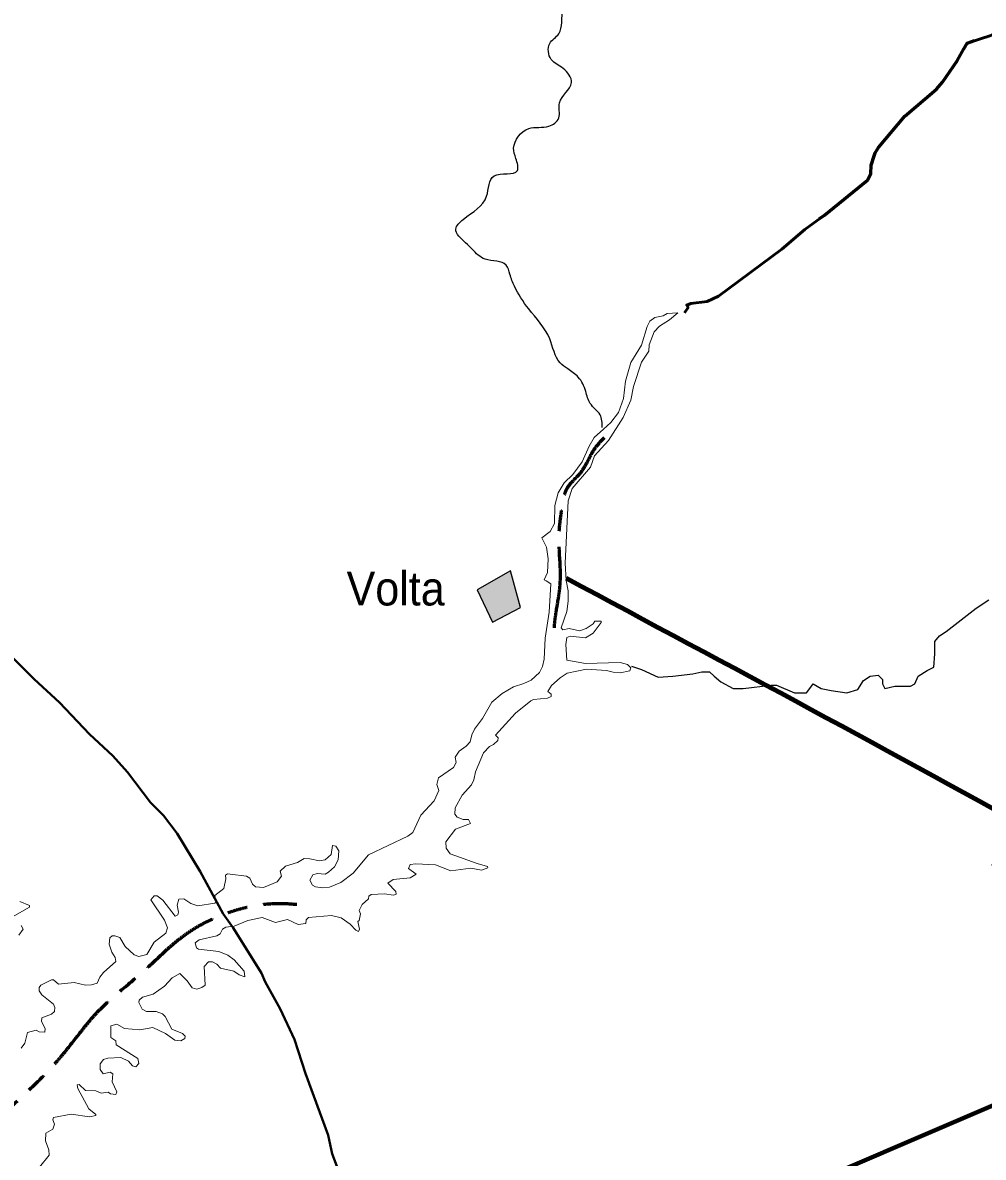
# Model space of a CAD drawing. Extents: x 553962 to 842807, y 8883888 to 9032388.
# Drawn here: x 584685 to 598851, y 8968659 to 8985392 of the extents above; entities that cross this region are included whole.
import ezdxf

# ---------------------------------------------------------------- set-up
doc = ezdxf.new("R2010")
doc.units = 0
doc.header["$LTSCALE"] = 200
doc.linetypes.add('LONG_DASH_SHORT_DASH', pattern=[9.9, 6, -1.2, 1.5, -1.2])
for name, color, linetype, lineweight in [('12', 7, 'Continuous', 25), ('21', 7, 'Continuous', 25), ('24', 7, 'Continuous', 25), ('25', 7, 'Continuous', 13), ('28', 7, 'Continuous', 40), ('41', 7, 'Continuous', 40), ('7', 7, 'LONG_DASH_SHORT_DASH', 60), ('9', 7, 'Continuous', 90)]:
    doc.layers.add(name, color=color, linetype=linetype, lineweight=lineweight)

msp = doc.modelspace()

# ---------------------------------------------------------------- hatches: boundary and pattern name
at = {"layer": '21'}
msp.add_hatch(color=256, dxfattribs=at).paths.add_polyline_path([(591387.2, 8977029.8), (591614.3, 8976550.1), (592028.7, 8976768.6), (591880.1, 8977309.9)])

# ---------------------------------------------------------------- linework, layer by layer
at = {"layer": '12', "lineweight": 40}
msp.add_lwpolyline([(584414.4, 8976152.1), (584852.4, 8975709.9), (585227.8, 8975368.9), (585671, 8974897.7), (586014.6, 8974582.2), (586230.8, 8974340.1), (586568.3, 8973894.4), (586761.1, 8973701.7), (586961.6, 8973436.3), (587301, 8972874.3), (587640.4, 8972251.7), (587788.5, 8972042.4), (588207.4, 8971376.7), (588263.1, 8971248.8), (588483.5, 8970850.8), (588695.4, 8970396.6), (588857.5, 8969895.4), (589190.3, 8968987.7), (589251, 8968710.7), (589674.6, 8967582.3)], dxfattribs=at)
at = {"layer": '21'}
msp.add_lwpolyline([(591387.2, 8977029.8), (591614.3, 8976550.1), (592028.7, 8976768.6), (591880.1, 8977309.9)], close=True, dxfattribs=at)
at = {"layer": '24', "lineweight": 53}
for points in [[(598562.6, 8985004.4), (598611, 8985091.4), (598961, 8985203.4), (599114.5, 8985297), (599176.5, 8985365.4)], [(597241.4, 8983430.3), (597255.2, 8983474), (597303.8, 8983551.2), (597693.6, 8984012), (598158.8, 8984413.5), (598250.1, 8984513.3), (598466.9, 8984832.2), (598562.6, 8985004.4)], [(597144.4, 8983071.7), (597192.6, 8983165.7), (597196.6, 8983289.5), (597241.4, 8983430.3)], [(594445, 8981112.5), (594498.6, 8981193.2), (594478.9, 8981228.6), (594539.1, 8981252.5), (594781.2, 8981282.3), (594943.8, 8981357.5), (595881.6, 8982053.4), (596221.2, 8982344.2), (596509.3, 8982553.5), (597144.4, 8983071.7)]]:
    msp.add_lwpolyline(points, dxfattribs=at)
at = {"layer": '24'}
msp.add_lwpolyline([(593663, 8975903.4), (593811, 8975854), (594057.8, 8975738.8), (594271.7, 8975755.3), (594567.8, 8975788.2), (594699.4, 8975821.1), (594814.5, 8975821.1), (594880.3, 8975755.3), (594979, 8975673), (595160, 8975574.2), (595308.1, 8975574.2), (595719.3, 8975623.6), (595801.6, 8975623.6), (596064.8, 8975508.3), (596163.5, 8975508.3), (596245.7, 8975508.3), (596295.1, 8975574.2), (596344.4, 8975640), (596459.6, 8975574.2), (596607.7, 8975541.3), (596838, 8975508.3), (597002.5, 8975557.7), (597084.7, 8975689.4), (597183.4, 8975755.3), (597298.6, 8975771.7), (597364.4, 8975705.9), (597364.4, 8975640), (597397.3, 8975574.2), (597545.3, 8975607.1), (597627.6, 8975607.1), (597775.7, 8975607.1), (597841.5, 8975640), (597890.8, 8975755.3), (598022.4, 8975837.6), (598121.1, 8975887), (598137.6, 8976084.5), (598137.6, 8976265.6), (598203.4, 8976347.9), (598302.1, 8976413.7), (598746.2, 8976759.4), (598932.5, 8976878.8)], dxfattribs=at)
msp.add_spline([(593232.1, 8979422.6), (593198.8, 8979610.9), (593054.8, 8979777.1), (592988.4, 8979954.4), (592877.6, 8980164.9), (592722.6, 8980286.8), (592611.8, 8980375.4), (592456.8, 8980729.9), (592146.7, 8981173.1), (591936.2, 8981505.4), (591869.8, 8981682.7), (591814.4, 8981815.7), (591504.3, 8981904.3), (591316, 8982048.3), (591216.4, 8982148), (591072.4, 8982347.5), (591183.1, 8982491.5), (591526.5, 8982834.9), (591637.2, 8983134.1), (591980.6, 8983211.6), (591958.4, 8983388.9), (591925.2, 8983544), (592146.7, 8983832), (592445.7, 8983865.3), (592589.7, 8983987.2), (592600.8, 8984208.7), (592778, 8984507.9), (592656.1, 8984718.4), (592478.9, 8984851.3), (592456.8, 8985084), (592589.7, 8985228), (592634, 8985394.2), (592645.1, 8985826.3), (592645.1, 8985970.3), (592467.9, 8986191.9), (592423.5, 8986763.6), (592224.2, 8987206.8), (592124.5, 8987461.6), (591847.6, 8987760.7), (591604, 8988037.7), (591482.1, 8988436.5), (591360.3, 8988702.4), (590950.5, 8989079.1), (590806.6, 8989256.4), (590518.6, 8989245.3), (590341.4, 8989422.6), (590031.3, 8989610.9), (589676.9, 8989721.7)], degree=3, dxfattribs=at)
at = {"layer": '25'}
for points in [[(594348, 8981113.9), (594348, 8981113.9), (594223.4, 8981008.9), (594075.8, 8980918.9), (593999.5, 8980834.1), (593923.2, 8980641.1), (593918.7, 8980549.5), (593810.5, 8980383.8), (593691.6, 8980027.2), (593653.2, 8979823), (593541.1, 8979568.9), (593541.1, 8979568.9), (593326.1, 8979230.3), (593118.1, 8979003.2), (593056.2, 8978837.1), (592788.7, 8978522.9), (592727, 8978339.3), (592684.6, 8977422.8), (592701.6, 8977167.9), (592731.3, 8977014.7), (592731.4, 8976862.7), (592710.1, 8976709.1), (592625.3, 8976466.7), (592653, 8976439.2), (592742.2, 8976458.1), (592894.9, 8976424.2), (592992.8, 8976460.4), (593098.8, 8976528.3), (593123.6, 8976567.4), (593214.3, 8976567.6), (593214.6, 8976559.7)], [(594348, 8981113.9), (594348, 8981113.9), (594223.4, 8981008.9), (594075.8, 8980918.9), (593999.5, 8980834.1), (593923.2, 8980641.1), (593918.7, 8980549.5), (593810.5, 8980383.8), (593691.6, 8980027.2), (593653.2, 8979823), (593541.1, 8979568.9), (593541.1, 8979568.9), (593326.1, 8979230.3), (593118.1, 8979003.2), (593056.2, 8978837.1), (592788.7, 8978522.9), (592727, 8978339.3), (592684.6, 8977422.8), (592701.6, 8977167.9), (592731.3, 8977014.7), (592731.4, 8976862.7), (592710.1, 8976709.1), (592625.3, 8976466.7), (592653, 8976439.2), (592742.2, 8976458.1), (592894.9, 8976424.2), (592992.8, 8976460.4), (593098.8, 8976528.3), (593123.6, 8976567.4), (593214.3, 8976567.6), (593214.6, 8976559.7)], [(593249.5, 8979396.5), (593358, 8979493.7), (593470.6, 8979644.5), (593544.9, 8979848.5), (593574.7, 8980103.6), (593653.1, 8980383.1), (593812.7, 8980635), (593893.2, 8980910.4), (593931.4, 8980988.9), (594007.8, 8981044.3), (594131.2, 8981067.8), (594188.7, 8981102), (594348, 8981113.9)], [(593249.5, 8979396.5), (593358, 8979493.7), (593470.6, 8979644.5), (593544.9, 8979848.5), (593574.7, 8980103.6), (593653.1, 8980383.1), (593812.7, 8980635), (593893.2, 8980910.4), (593931.4, 8980988.9), (594007.8, 8981044.3), (594131.2, 8981067.8), (594188.7, 8981102), (594348, 8981113.9)], [(592340.2, 8977796.1), (592463.6, 8977889.9), (592529.4, 8978006.6), (592531.7, 8978272), (592582.8, 8978459.4), (592672, 8978608.1), (592799.5, 8978729.2), (592937.2, 8978913.6), (593037.2, 8979147.4), (593113.6, 8979274.7), (593249.5, 8979396.5)], [(592340.2, 8977796.1), (592463.6, 8977889.9), (592529.4, 8978006.6), (592531.7, 8978272), (592582.8, 8978459.4), (592672, 8978608.1), (592799.5, 8978729.2), (592937.2, 8978913.6), (593037.2, 8979147.4), (593113.6, 8979274.7), (593249.5, 8979396.5)], [(592403.5, 8977160.8), (592376.8, 8977178.1), (592423.3, 8977282.6), (592436.1, 8977486), (592410.8, 8977655.4), (592340.2, 8977796.1)], [(592403.5, 8977160.8), (592376.8, 8977178.1), (592423.3, 8977282.6), (592436.1, 8977486), (592410.8, 8977655.4), (592340.2, 8977796.1)], [(589256.8, 8973257.4), (589304.8, 8973250.5), (589349.5, 8973181.3), (589336.7, 8973046.6), (589282, 8972943.2), (589197.1, 8972864.3), (589143.7, 8972836.4), (589028.8, 8972846.9), (588963.2, 8972823.6), (588920.5, 8972745), (588956.7, 8972674.9), (589003.3, 8972647.2), (589105, 8972632.4), (589208.9, 8972641.3), (589377.1, 8972711), (589557.5, 8972848.9), (589783.1, 8973121.1), (590364.9, 8973397.1), (590439.2, 8973448.1), (590558.2, 8973707.2), (590751.6, 8973917.8), (590821.5, 8974070.5), (590792, 8974157.8), (590815.2, 8974257.2), (591040.4, 8974410.4), (591076.5, 8974482.4), (591063.8, 8974558.8), (591121.2, 8974648.3), (591227.2, 8974720.4), (591282.6, 8974788.8), (591308.2, 8974890.7), (591350.1, 8974974.6), (591465.3, 8975128.4), (591603.2, 8975370.3), (591756.1, 8975500), (591922, 8975597.8), (592075.7, 8975644.8), (592185.6, 8975697.8), (592308.6, 8975810.4), (592349.1, 8975899.9), (592374.4, 8976007.6), (592391.5, 8976313.7), (592449, 8976697.9), (592471.9, 8977116.8), (592403.5, 8977160.8)], [(589256.8, 8973257.4), (589304.8, 8973250.5), (589349.5, 8973181.3), (589336.7, 8973046.6), (589282, 8972943.2), (589197.1, 8972864.3), (589143.7, 8972836.4), (589028.8, 8972846.9), (588963.2, 8972823.6), (588920.5, 8972745), (588956.7, 8972674.9), (589003.3, 8972647.2), (589105, 8972632.4), (589208.9, 8972641.3), (589377.1, 8972711), (589557.5, 8972848.9), (589783.1, 8973121.1), (590364.9, 8973397.1), (590439.2, 8973448.1), (590558.2, 8973707.2), (590751.6, 8973917.8), (590821.5, 8974070.5), (590792, 8974157.8), (590815.2, 8974257.2), (591040.4, 8974410.4), (591076.5, 8974482.4), (591063.8, 8974558.8), (591121.2, 8974648.3), (591227.2, 8974720.4), (591282.6, 8974788.8), (591308.2, 8974890.7), (591350.1, 8974974.6), (591465.3, 8975128.4), (591603.2, 8975370.3), (591756.1, 8975500), (591922, 8975597.8), (592075.7, 8975644.8), (592185.6, 8975697.8), (592308.6, 8975810.4), (592349.1, 8975899.9), (592374.4, 8976007.6), (592391.5, 8976313.7), (592449, 8976697.9), (592471.9, 8977116.8), (592403.5, 8977160.8)], [(593214.6, 8976559.7), (593215.2, 8976544.7), (593099, 8976390.4), (592986.9, 8976322.5), (592758.7, 8976343.4), (592708.2, 8976324.4), (592695.2, 8976224.5), (592709.9, 8975991.5), (592983.9, 8975944.1), (593493.9, 8975956.8), (593602.1, 8975927.4), (593649.1, 8975881.7)], [(593214.6, 8976559.7), (593215.2, 8976544.7), (593099, 8976390.4), (592986.9, 8976322.5), (592758.7, 8976343.4), (592708.2, 8976324.4), (592695.2, 8976224.5), (592709.9, 8975991.5), (592983.9, 8975944.1), (593493.9, 8975956.8), (593602.1, 8975927.4), (593649.1, 8975881.7)], [(593649.1, 8975881.7), (593655, 8975876), (593638.1, 8975835.7), (593493.9, 8975806), (593392, 8975812.4), (593294, 8975840), (593001.4, 8975857), (592713.8, 8975797.2), (592610.3, 8975731.6), (592482.8, 8975616.5), (592429.9, 8975529.9), (592480.5, 8975487.5), (592478.3, 8975455.5), (592423.1, 8975432.1), (592219.4, 8975410.8), (592178.8, 8975393.7), (591951.5, 8975211), (591658.9, 8974884.4), (591696.9, 8974843.5), (591690.4, 8974805.5), (591629, 8974746.2), (591569.4, 8974716.2), (591482.2, 8974622.5), (591361.3, 8974342.6), (591339.9, 8974225.6), (591302.4, 8974150.2), (591167.7, 8974002.3), (591061.7, 8973815.6), (591059.6, 8973722.4), (591091.3, 8973677.8), (591182.8, 8973643.6), (591261.3, 8973639.2), (591286.8, 8973584.3), (591065.8, 8973500.9), (590925.8, 8973310), (590930.2, 8973216.3), (590989.7, 8973133.6), (591386.4, 8972993.6), (591539.1, 8972948.4), (591544.1, 8972929.1)], [(593649.1, 8975881.7), (593655, 8975876), (593638.1, 8975835.7), (593493.9, 8975806), (593392, 8975812.4), (593294, 8975840), (593001.4, 8975857), (592713.8, 8975797.2), (592610.3, 8975731.6), (592482.8, 8975616.5), (592429.9, 8975529.9), (592480.5, 8975487.5), (592478.3, 8975455.5), (592423.1, 8975432.1), (592219.4, 8975410.8), (592178.8, 8975393.7), (591951.5, 8975211), (591658.9, 8974884.4), (591696.9, 8974843.5), (591690.4, 8974805.5), (591629, 8974746.2), (591569.4, 8974716.2), (591482.2, 8974622.5), (591361.3, 8974342.6), (591339.9, 8974225.6), (591302.4, 8974150.2), (591167.7, 8974002.3), (591061.7, 8973815.6), (591059.6, 8973722.4), (591091.3, 8973677.8), (591182.8, 8973643.6), (591261.3, 8973639.2), (591286.8, 8973584.3), (591065.8, 8973500.9), (590925.8, 8973310), (590930.2, 8973216.3), (590989.7, 8973133.6), (591386.4, 8972993.6), (591539.1, 8972948.4), (591544.1, 8972929.1)], [(587744.4, 8972835.9), (587983.9, 8972804.3), (588036.8, 8972776.6), (588075, 8972687.6), (588119.6, 8972647.3), (588237.5, 8972640.8), (588435.9, 8972723.7), (588499.7, 8972804.5), (588483.1, 8972879), (588561.7, 8972951.1), (588739.8, 8973006.3), (588835.7, 8973065.7), (588918.6, 8973063.5), (589063, 8973031.8), (589147.9, 8973046.8), (589234.5, 8973124.8), (589252.7, 8973258), (589256.8, 8973257.4)], [(587744.4, 8972835.9), (587983.9, 8972804.3), (588036.8, 8972776.6), (588075, 8972687.6), (588119.6, 8972647.3), (588237.5, 8972640.8), (588435.9, 8972723.7), (588499.7, 8972804.5), (588483.1, 8972879), (588561.7, 8972951.1), (588739.8, 8973006.3), (588835.7, 8973065.7), (588918.6, 8973063.5), (589063, 8973031.8), (589147.9, 8973046.8), (589234.5, 8973124.8), (589252.7, 8973258), (589256.8, 8973257.4)], [(591544.1, 8972929.1), (591451.2, 8972895.9), (591293, 8972921.2), (591000.3, 8972885.2), (590771.4, 8972974.2), (590482, 8972987.1), (590400.9, 8972976.4), (590375.5, 8972917.5), (590487.9, 8972834.1), (590400.8, 8972781.1), (590146.4, 8972755.6), (590069.9, 8972700.4), (590188.4, 8972581.5), (590190.6, 8972539), (590153.7, 8972526.2), (590022.9, 8972543.1), (589823.3, 8972534.6), (589789.5, 8972511.4), (589784.9, 8972471), (589689.6, 8972386.1), (589647, 8972301.2), (589666, 8972251.4), (589644.9, 8972152.7), (589627.8, 8972139.3), (589651.2, 8972025), (589636.7, 8971991.2), (589636.7, 8971991.2)], [(591544.1, 8972929.1), (591451.2, 8972895.9), (591293, 8972921.2), (591000.3, 8972885.2), (590771.4, 8972974.2), (590482, 8972987.1), (590400.9, 8972976.4), (590375.5, 8972917.5), (590487.9, 8972834.1), (590400.8, 8972781.1), (590146.4, 8972755.6), (590069.9, 8972700.4), (590188.4, 8972581.5), (590190.6, 8972539), (590153.7, 8972526.2), (590022.9, 8972543.1), (589823.3, 8972534.6), (589789.5, 8972511.4), (589784.9, 8972471), (589689.6, 8972386.1), (589647, 8972301.2), (589666, 8972251.4), (589644.9, 8972152.7), (589627.8, 8972139.3), (589651.2, 8972025), (589636.7, 8971991.2), (589636.7, 8971991.2)], [(585111.6, 8971279.2), (585141.3, 8971274.9), (585213.8, 8971211.3), (585443, 8971236.7), (585613.2, 8971196.4), (585698.2, 8971200.7), (585782.6, 8971228.1), (585821.2, 8971315.3), (585878.5, 8971385.4), (586058.9, 8971546.7), (586050.5, 8971606.3), (585999.6, 8971687.1), (585961.4, 8971801.8), (585969.8, 8971897.1), (586004, 8971925.1), (586046.1, 8971927.1), (586118.5, 8971901.5), (586197.3, 8971767.6), (586326.8, 8971644.7), (586399.8, 8971621.3), (586515.7, 8971651), (586626.4, 8971831.7), (586793.9, 8971963.1), (586819.5, 8972043.7), (586777.5, 8972158), (586575.5, 8972456.3), (586626.1, 8972513.3), (586666.5, 8972513.3), (586751.7, 8972453.7), (586934.4, 8972216.2), (586974.5, 8972237.3), (586982.9, 8972274.7), (586964.1, 8972379.9), (586989.7, 8972468.8), (587061.7, 8972470.9), (587164.3, 8972404.8), (587265.6, 8972369), (587521, 8972409.7), (587521, 8972409.7), (587537.4, 8972424.4), (587520.6, 8972519.8), (587652.2, 8972626), (587681.8, 8972766), (587674.8, 8972821.7), (587705.8, 8972841), (587744.4, 8972835.9)], [(585111.6, 8971279.2), (585141.3, 8971274.9), (585213.8, 8971211.3), (585443, 8971236.7), (585613.2, 8971196.4), (585698.2, 8971200.7), (585782.6, 8971228.1), (585821.2, 8971315.3), (585878.5, 8971385.4), (586058.9, 8971546.7), (586050.5, 8971606.3), (585999.6, 8971687.1), (585961.4, 8971801.8), (585969.8, 8971897.1), (586004, 8971925.1), (586046.1, 8971927.1), (586118.5, 8971901.5), (586197.3, 8971767.6), (586326.8, 8971644.7), (586399.8, 8971621.3), (586515.7, 8971651), (586626.4, 8971831.7), (586793.9, 8971963.1), (586819.5, 8972043.7), (586777.5, 8972158), (586575.5, 8972456.3), (586626.1, 8972513.3), (586666.5, 8972513.3), (586751.7, 8972453.7), (586934.4, 8972216.2), (586974.5, 8972237.3), (586982.9, 8972274.7), (586964.1, 8972379.9), (586989.7, 8972468.8), (587061.7, 8972470.9), (587164.3, 8972404.8), (587265.6, 8972369), (587521, 8972409.7), (587521, 8972409.7), (587537.4, 8972424.4), (587520.6, 8972519.8), (587652.2, 8972626), (587681.8, 8972766), (587674.8, 8972821.7), (587705.8, 8972841), (587744.4, 8972835.9)], [(584644.6, 8972432.6), (584786.6, 8972370.8), (584785.8, 8972347.3), (584395, 8972126.3)], [(584644.6, 8972432.6), (584786.6, 8972370.8), (584785.8, 8972347.3), (584395, 8972126.3)], [(589636.7, 8971991.2), (589598.1, 8972007.9), (589513.3, 8972099), (589381.6, 8972192.5), (589241.4, 8972224.5), (588901.3, 8972196.8), (588865.3, 8972162.9), (588863, 8972107.8), (588748.1, 8972092.9), (588748.1, 8972092.9), (588590.9, 8972165), (588412.8, 8972122.6), (588217.3, 8972196.9), (588004.9, 8972152.3), (587806, 8972067.6), (587682, 8972052.4), (587633.2, 8972022.7), (587596.9, 8971954.8), (587546.7, 8971925.3), (587289, 8971866.3), (587229.6, 8971820.7), (587248.6, 8971751), (587275.8, 8971727.9), (587576, 8971693.4), (587711.7, 8971638.2), (587803.3, 8971572.2), (587950.9, 8971402.7), (587960.4, 8971321.1)], [(589636.7, 8971991.2), (589598.1, 8972007.9), (589513.3, 8972099), (589381.6, 8972192.5), (589241.4, 8972224.5), (588901.3, 8972196.8), (588865.3, 8972162.9), (588863, 8972107.8), (588748.1, 8972092.9), (588748.1, 8972092.9), (588590.9, 8972165), (588412.8, 8972122.6), (588217.3, 8972196.9), (588004.9, 8972152.3), (587806, 8972067.6), (587682, 8972052.4), (587633.2, 8972022.7), (587596.9, 8971954.8), (587546.7, 8971925.3), (587289, 8971866.3), (587229.6, 8971820.7), (587248.6, 8971751), (587275.8, 8971727.9), (587576, 8971693.4), (587711.7, 8971638.2), (587803.3, 8971572.2), (587950.9, 8971402.7), (587960.4, 8971321.1)], [(584661.4, 8972077.8), (584690.8, 8972022.3), (584629.4, 8971933.2)], [(584661.4, 8972077.8), (584690.8, 8972022.3), (584629.4, 8971933.2)], [(587960.4, 8971321.1), (587960.4, 8971321.1), (587878.2, 8971348.9), (587800.7, 8971404.6), (587601.6, 8971447), (587546.2, 8971506.3), (587484.6, 8971544.6), (587424.8, 8971542.6), (587359.2, 8971474.4), (587373.9, 8971198.8), (587329.3, 8971162.4), (587253.1, 8971141.2), (587184.9, 8971158.2), (587112.5, 8971262.4), (587002, 8971368.3), (586889.7, 8971306.8), (586777.2, 8971181.7), (586606.9, 8971064.6), (586453.7, 8971019.6), (586403.3, 8970977.5), (586399, 8970942.1), (586445.6, 8970844.1), (586509.4, 8970807.7), (586653.8, 8970811.9), (586747.1, 8970773.8), (586785.6, 8970735.2), (586885.5, 8970550.7), (587042.4, 8970487), (587082.7, 8970444.8), (587078.6, 8970412.6), (587019.2, 8970376.5), (586928.2, 8970384.9), (586793.3, 8970485.2), (586602.9, 8970571.8), (586411.7, 8970540), (586184.3, 8970557.1), (586072, 8970620.6), (585986.8, 8970597.1), (585985.1, 8970426.9), (586057, 8970376.2), (586064.4, 8970318.2), (586383.6, 8970117.6), (586398.9, 8970043.2), (586352.2, 8969994.2), (586303.6, 8970008.9), (586245.3, 8970079.5), (586131.1, 8970130), (585940.1, 8970123.6), (585874.5, 8970100.3), (585827.6, 8970038.4), (585830, 8969952.9), (585872.2, 8969890), (585973.9, 8969915.4), (586012.3, 8969889.7), (586006, 8969772.9), (586071.7, 8969626.7), (586056.7, 8969586.3), (585978.4, 8969594.8), (585945.9, 8969618), (585842.4, 8969605.4), (585761.7, 8969641.4), (585609, 8969645.7), (585519.5, 8969734.8), (585490.3, 8969728.7), (585498.3, 8969673.3), (585661.4, 8969372.5), (585765.4, 8969291.4), (585763.8, 8969274.2), (585672.2, 8969254.8), (585400.5, 8969295.2), (585139.6, 8969248.4), (585128.7, 8969210.2), (585151.9, 8969146.5), (585128.6, 8969076.5), (585026.8, 8969016.8), (585022.1, 8968902.1), (585069.3, 8968771.8), (585077.6, 8968692.1), (584933.7, 8968514.1)], [(587960.4, 8971321.1), (587960.4, 8971321.1), (587878.2, 8971348.9), (587800.7, 8971404.6), (587601.6, 8971447), (587546.2, 8971506.3), (587484.6, 8971544.6), (587424.8, 8971542.6), (587359.2, 8971474.4), (587373.9, 8971198.8), (587329.3, 8971162.4), (587253.1, 8971141.2), (587184.9, 8971158.2), (587112.5, 8971262.4), (587002, 8971368.3), (586889.7, 8971306.8), (586777.2, 8971181.7), (586606.9, 8971064.6), (586453.7, 8971019.6), (586403.3, 8970977.5), (586399, 8970942.1), (586445.6, 8970844.1), (586509.4, 8970807.7), (586653.8, 8970811.9), (586747.1, 8970773.8), (586785.6, 8970735.2), (586885.5, 8970550.7), (587042.4, 8970487), (587082.7, 8970444.8), (587078.6, 8970412.6), (587019.2, 8970376.5), (586928.2, 8970384.9), (586793.3, 8970485.2), (586602.9, 8970571.8), (586411.7, 8970540), (586184.3, 8970557.1), (586072, 8970620.6), (585986.8, 8970597.1), (585985.1, 8970426.9), (586057, 8970376.2), (586064.4, 8970318.2), (586383.6, 8970117.6), (586398.9, 8970043.2), (586352.2, 8969994.2), (586303.6, 8970008.9), (586245.3, 8970079.5), (586131.1, 8970130), (585940.1, 8970123.6), (585874.5, 8970100.3), (585827.6, 8970038.4), (585830, 8969952.9), (585872.2, 8969890), (585973.9, 8969915.4), (586012.3, 8969889.7), (586006, 8969772.9), (586071.7, 8969626.7), (586056.7, 8969586.3), (585978.4, 8969594.8), (585945.9, 8969618), (585842.4, 8969605.4), (585761.7, 8969641.4), (585609, 8969645.7), (585519.5, 8969734.8), (585490.3, 8969728.7), (585498.3, 8969673.3), (585661.4, 8969372.5), (585765.4, 8969291.4), (585763.8, 8969274.2), (585672.2, 8969254.8), (585400.5, 8969295.2), (585139.6, 8969248.4), (585128.7, 8969210.2), (585151.9, 8969146.5), (585128.6, 8969076.5), (585026.8, 8969016.8), (585022.1, 8968902.1), (585069.3, 8968771.8), (585077.6, 8968692.1), (584933.7, 8968514.1)], [(584662.6, 8970267.9), (584714.5, 8970340.6), (584757.2, 8970501.8), (584885.6, 8970535.6), (584929, 8970508.2), (585011.6, 8970506.1), (585015.9, 8970557.2), (584963, 8970661.1), (584969.3, 8970716), (585111.8, 8970769.6), (585154, 8970809.8), (585158.3, 8970866.9), (585141.3, 8970915.8), (584965.3, 8971056), (584926.9, 8971113.6), (584926.9, 8971162.3), (584954.3, 8971200.4), (585111.6, 8971279.2)], [(584662.6, 8970267.9), (584714.5, 8970340.6), (584757.2, 8970501.8), (584885.6, 8970535.6), (584929, 8970508.2), (585011.6, 8970506.1), (585015.9, 8970557.2), (584963, 8970661.1), (584969.3, 8970716), (585111.8, 8970769.6), (585154, 8970809.8), (585158.3, 8970866.9), (585141.3, 8970915.8), (584965.3, 8971056), (584926.9, 8971113.6), (584926.9, 8971162.3), (584954.3, 8971200.4), (585111.6, 8971279.2)]]:
    msp.add_lwpolyline(points, dxfattribs=at)
at = {"layer": '28', "lineweight": 80}
msp.add_lwpolyline([(596480.2, 8968348.2), (600111.2, 8969905.3), (599003, 8972985.3)], dxfattribs=at)
at = {"layer": '7'}
for points in [[(597241.4, 8983430.3), (597255.2, 8983474), (597303.8, 8983551.2), (597693.6, 8984012), (598158.8, 8984413.5), (598250.1, 8984513.3), (598466.9, 8984832.2), (598562.6, 8985004.4)], [(598562.6, 8985004.4), (598611, 8985091.4), (598722.8, 8985127.2)], [(597144.4, 8983071.7), (597192.6, 8983165.7), (597196.6, 8983289.5), (597241.4, 8983430.3)], [(596432.2, 8982497.4), (596509.3, 8982553.5), (597144.4, 8983071.7)]]:
    msp.add_lwpolyline(points, dxfattribs=at)
for points in [[(592525.2, 8976466.9), (592528.1, 8976506.5), (592612.5, 8977139.6), (592595.6, 8977840.2), (592646.2, 8978279.2), (592713.7, 8978524), (592916.2, 8978760.3), (593118.7, 8979106.4), (593264.9, 8979274.8)], [(583719.8, 8968683.1), (584226, 8969147.1), (585263.8, 8970159.6), (585803.8, 8970817.7), (586453.4, 8971391.4), (587077.8, 8971939.8), (587744.3, 8972277.3), (588469.9, 8972403.9), (588728.8, 8972391.8)]]:
    msp.add_spline(points, degree=3, dxfattribs=at)
at = {"layer": '9'}
msp.add_spline([(592698.5, 8977198.4), (599903.5, 8973292.7), (608459.2, 8968138.2), (612674.8, 8965332.6), (616842, 8962096.4), (620005, 8958671.2), (621134, 8957974.7), (621473.4, 8956805.3), (621586.2, 8956597.5)], degree=3, dxfattribs=at)

# ---------------------------------------------------------------- texts
at = {"layer": '41', "width": 0.95}
msp.add_text('Volta', height=500, dxfattribs=at).set_placement((589461.3, 8976797.6))

doc.saveas('drawing.dxf')
